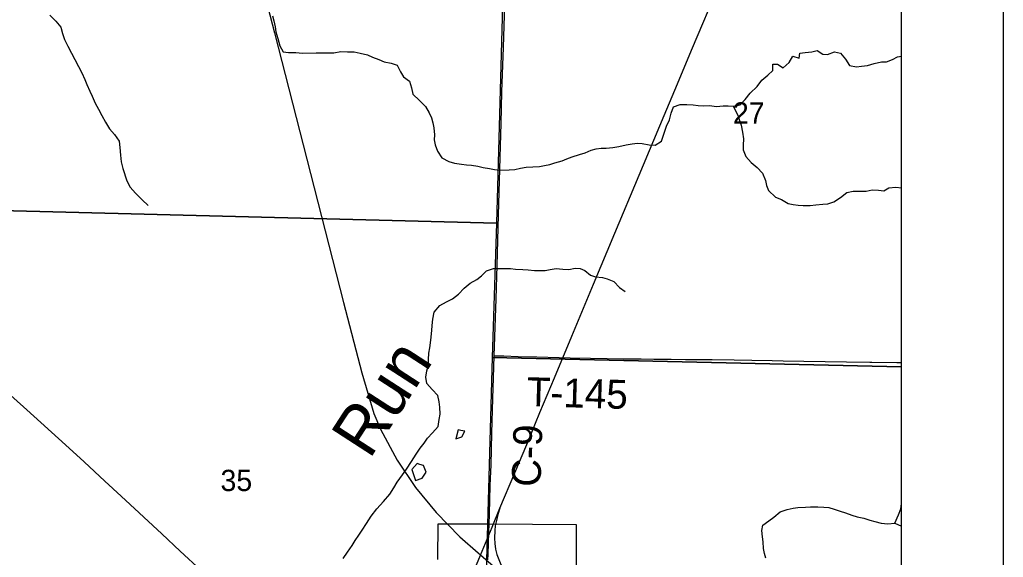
# Model space of a CAD drawing. Extents: x 0 to 34, y 0 to 22.
# Drawn here: x 7.066 to 9, y 15.96 to 17.017 of the extents above; entities that cross this region are included whole.
import ezdxf

# ---------------------------------------------------------------- set-up
doc = ezdxf.new("R2010")
doc.units = 0
for name, color, linetype in [('Default', 7, 'Continuous'), ('GM_X_City_Street', 7, 'Continuous'), ('GM_X_Corporation', 7, 'Continuous'), ('GM_X_County_Road', 7, 'Continuous'), ('GM_X_County_Road_Text', 7, 'Continuous'), ('GM_X_Interchange_Ramps', 7, 'Continuous'), ('GM_X_Major_River', 7, 'Continuous'), ('GM_X_Major_River_Text', 7, 'Continuous'), ('GM_X_Minor_River', 7, 'Continuous'), ('GM_X_Minor_River_Text', 7, 'Continuous'), ('GM_X_Section', 7, 'Continuous'), ('GM_X_Unincorporated_Location', 7, 'Continuous'), ('GM_X_US_Shield', 7, 'Continuous'), ('SH_Cut_Line', 7, 'Continuous'), ('SH_Text', 7, 'Continuous')]:
    doc.layers.add(name, color=color, linetype=linetype)

msp = doc.modelspace()

# ---------------------------------------------------------------- linework, layer by layer
at = {"layer": 'Default'}
msp.add_lwpolyline([(8.8, 14), (8.8, 18.8069)], dxfattribs=at)
for points in [[(8.8, 16.334), (8.8, 17.3506), (8.0236, 17.3548), (8.0033, 16.6164), (7.9948, 16.3527)], [(8.8, 15.3246), (8.8, 16.334), (7.9948, 16.3527), (7.9737, 15.6015), (7.9679, 15.3374)]]:
    msp.add_lwpolyline(points, close=True, dxfattribs=at)
at = {"layer": 'GM_X_City_Street'}
for points in [[(7.9989, 16.356), (8.0025, 16.468), (8.0046, 16.5332), (8.0075, 16.6325), (8.0103, 16.7226), (8.0122, 16.7909), (8.0126, 16.8127), (8.0141, 16.8748), (8.017, 16.9617), (8.021, 17.0901)], [(7.989, 16.0249), (7.9895, 16.0453), (7.9911, 16.1012), (7.9927, 16.1416), (7.9943, 16.2037), (7.9964, 16.2721), (7.9976, 16.3125), (7.9989, 16.356)], [(7.9867, 15.9546), (7.9871, 15.9656), (7.9887, 16.009), (7.989, 16.0249)]]:
    msp.add_lwpolyline(points, dxfattribs=at)
at = {"layer": 'GM_X_Corporation'}
for p, q in [((7.9673, 15.9687), (7.9718, 15.9648)), ((7.9718, 15.9648), (8.0563, 15.8914))]:
    msp.add_line(p, q, dxfattribs=at)
for points in [[(6.5927, 20.8), (6.6173, 20.7022), (6.732, 20.2629), (6.8332, 19.8757), (6.9052, 19.5948), (7.0125, 19.1776), (7.1431, 18.6694), (7.2218, 18.3603), (7.335, 17.9018), (7.5012, 17.2442), (7.5672, 16.9911), (7.6376, 16.714), (7.7025, 16.4605), (7.7388, 16.3223), (7.7626, 16.2427), (7.7756, 16.2117), (7.8081, 16.1506), (7.8441, 16.0969), (7.8846, 16.0477), (7.9314, 15.9998), (7.9673, 15.9687)], [(7.9573, 15.9292), (7.972, 15.9642), (7.995, 16.0193), (8.0101, 16.0566), (8.0396, 16.1259), (8.063, 16.1817), (8.0889, 16.2441), (8.1175, 16.3124), (8.1518, 16.3948), (8.1945, 16.4965), (8.2364, 16.597), (8.2842, 16.7108), (8.3333, 16.828), (8.3542, 16.8783), (8.3889, 16.9613), (8.4405, 17.0841)], [(8.0101, 16.0566), (8.0064, 16.0438), (8.0032, 16.0324), (8.0011, 16.0214), (8, 16.0122), (7.9995, 15.9972), (8, 15.9869), (8.0018, 15.9759), (8.0044, 15.965), (8.008, 15.9554), (8.0122, 15.9455), (8.0171, 15.9362), (8.0217, 15.929), (8.0261, 15.9226), (8.0314, 15.9163), (8.0364, 15.9108), (8.0427, 15.9049), (8.0587, 15.8914), (8.5043, 15.5105), (8.8, 15.2581)]]:
    msp.add_lwpolyline(points, dxfattribs=at)
at = {"layer": 'GM_X_County_Road'}
msp.add_lwpolyline([(7.0027, 16.3195), (7.0291, 16.2956), (7.0799, 16.2498), (7.1558, 16.1809), (7.1925, 16.1473), (7.2336, 16.1094), (7.2657, 16.08), (7.3452, 16.0057), (7.3814, 15.9718), (7.4226, 15.9339), (7.4544, 15.9041), (7.4861, 15.8744), (7.4979, 15.8643), (7.5018, 15.8606), (7.5256, 15.8381), (7.5518, 15.8138)], dxfattribs=at)
at = {"layer": 'GM_X_Interchange_Ramps'}
msp.add_lwpolyline([(7.9989, 16.356), (8.0181, 16.3556), (8.0458, 16.3548), (8.083, 16.3539), (8.1265, 16.3527), (8.1482, 16.3522), (8.1886, 16.3511), (8.2538, 16.3501), (8.2879, 16.3496), (8.3128, 16.3493), (8.3469, 16.349), (8.3748, 16.3488), (8.4276, 16.3483), (8.4711, 16.3478), (8.5053, 16.3475), (8.5456, 16.3469), (8.5673, 16.3463), (8.6077, 16.3455), (8.6915, 16.3442), (8.7375, 16.3436), (8.7412, 16.3436), (8.7909, 16.3428), (8.8, 16.3427)], dxfattribs=at)
at = {"layer": 'GM_X_Major_River'}
for points in [[(7.9332, 16.209), (7.9281, 16.2101), (7.9236, 16.1926)], [(7.9236, 16.1926), (7.9354, 16.1964), (7.9411, 16.2074), (7.9332, 16.209)], [(7.8525, 16.1425), (7.8475, 16.144), (7.8368, 16.1326), (7.8444, 16.111)], [(7.8444, 16.111), (7.857, 16.1151), (7.865, 16.1269), (7.86, 16.1402), (7.8525, 16.1425)]]:
    msp.add_lwpolyline(points, dxfattribs=at)
at = {"layer": 'GM_X_Section'}
for points in [[(7.1254, 17.0258), (7.1372, 17.0137), (7.1467, 17.0019), (7.1502, 16.9894), (7.1544, 16.9777), (7.1609, 16.9644), (7.1681, 16.9512), (7.1742, 16.9387), (7.1815, 16.9247), (7.1884, 16.9122), (7.1941, 16.8993), (7.1979, 16.8891), (7.2037, 16.8762), (7.2086, 16.8664), (7.2147, 16.8524), (7.2209, 16.8406), (7.2277, 16.8285), (7.235, 16.8153), (7.2426, 16.802), (7.2525, 16.7907), (7.2613, 16.7778), (7.2632, 16.7653), (7.264, 16.7505), (7.2652, 16.7372), (7.2691, 16.7243), (7.2767, 16.7001), (7.2832, 16.6876), (7.2935, 16.6759), (7.3068, 16.6626), (7.3186, 16.6513)], [(7.5633, 17.0244), (7.5656, 17.0142), (7.5686, 17.0024), (7.5694, 16.9925), (7.5736, 16.9796), (7.5777, 16.9655), (7.5842, 16.9534), (7.5945, 16.9522), (7.6086, 16.9519), (7.6222, 16.9511), (7.6489, 16.9518), (7.6591, 16.9515), (7.6702, 16.9518), (7.6839, 16.9514), (7.6976, 16.9541), (7.7105, 16.9533), (7.7234, 16.9533), (7.7356, 16.9507), (7.7497, 16.9476), (7.7596, 16.9431), (7.7721, 16.9381), (7.7828, 16.9339), (7.7965, 16.9313), (7.8079, 16.9271), (7.8147, 16.9142), (7.8204, 16.9043), (7.8322, 16.8959), (7.8364, 16.883), (7.839, 16.8701), (7.852, 16.8575), (7.8641, 16.8458), (7.8714, 16.8336), (7.8755, 16.8237), (7.8782, 16.8142), (7.8801, 16.804), (7.8816, 16.7903), (7.8812, 16.7808), (7.8831, 16.7709), (7.8873, 16.7584), (7.8957, 16.7451), (7.9097, 16.7378), (7.9208, 16.7344), (7.9348, 16.7325), (7.9447, 16.7314), (7.9546, 16.7306), (7.9668, 16.7287), (7.9771, 16.726), (7.99, 16.7238), (7.9995, 16.7222), (8.0094, 16.7211), (8.0284, 16.7218), (8.0394, 16.7222), (8.0508, 16.7249), (8.0619, 16.7268), (8.0752, 16.7275), (8.0881, 16.7283), (8.098, 16.7302), (8.1083, 16.7317), (8.1182, 16.7351), (8.1323, 16.7393), (8.1418, 16.7431), (8.152, 16.7469), (8.1669, 16.7514), (8.1779, 16.7552), (8.1897, 16.7602), (8.1992, 16.7628), (8.2095, 16.7643), (8.219, 16.7643), (8.2319, 16.7655), (8.2437, 16.7674), (8.2582, 16.7704)], [(8.2582, 16.7704), (8.2704, 16.7727), (8.2806, 16.7742), (8.2901, 16.7734), (8.3035, 16.7708), (8.3156, 16.77), (8.3278, 16.778), (8.3312, 16.7875), (8.3347, 16.7977), (8.3377, 16.8072), (8.3434, 16.8201), (8.3468, 16.8327), (8.3518, 16.8456), (8.3644, 16.8498), (8.378, 16.8501), (8.3902, 16.8494), (8.3997, 16.8482), (8.4096, 16.8475), (8.4222, 16.8478), (8.4359, 16.8463), (8.4492, 16.8471), (8.4587, 16.8474), (8.469, 16.8467), (8.4827, 16.8493), (8.4925, 16.8596), (8.5024, 16.8725), (8.5158, 16.8854), (8.5249, 16.8976), (8.5371, 16.9078), (8.547, 16.9166), (8.5466, 16.9295), (8.5561, 16.9291), (8.5671, 16.9222), (8.5789, 16.9325), (8.5858, 16.9447), (8.5983, 16.9412), (8.6002, 16.9507), (8.6105, 16.9522), (8.6234, 16.9534), (8.6337, 16.956), (8.6451, 16.9492), (8.6546, 16.9481), (8.668, 16.9534), (8.6801, 16.9507), (8.69, 16.9389), (8.6976, 16.9268), (8.7113, 16.9237), (8.7212, 16.9256), (8.733, 16.9264), (8.7459, 16.9305), (8.7604, 16.934), (8.7703, 16.934), (8.7821, 16.9385), (8.7916, 16.9438), (8.8, 16.945)], [(8.469, 16.8467), (8.4777, 16.8292), (8.4815, 16.8186), (8.4845, 16.8091), (8.4872, 16.7958), (8.4891, 16.7825), (8.4887, 16.7703), (8.4887, 16.7608), (8.4936, 16.7475), (8.5039, 16.7361), (8.5157, 16.7262), (8.5263, 16.7148), (8.5324, 16.7004), (8.5343, 16.6909), (8.5385, 16.681), (8.5522, 16.6677), (8.5636, 16.6631), (8.5769, 16.6555), (8.5868, 16.6532), (8.5967, 16.6521), (8.6062, 16.6513), (8.6199, 16.6517), (8.6313, 16.6528), (8.645, 16.654), (8.6549, 16.6547), (8.6667, 16.6585), (8.6796, 16.6669), (8.6922, 16.6771), (8.7047, 16.6798), (8.7177, 16.6794), (8.7302, 16.6794), (8.7424, 16.6824), (8.7546, 16.6817), (8.7652, 16.6805), (8.7751, 16.6862), (8.7888, 16.6877), (8.8, 16.6859)], [(7.8742, 16.3868), (7.8765, 16.4058), (7.8773, 16.4157), (7.878, 16.4278), (7.8807, 16.4415), (7.8921, 16.4548), (7.9054, 16.462), (7.9168, 16.4677), (7.9286, 16.4768), (7.9397, 16.489), (7.9515, 16.4985), (7.9648, 16.5057), (7.9743, 16.5133), (7.9838, 16.5228), (7.9975, 16.5273), (8.031, 16.5273), (8.0409, 16.5265), (8.0553, 16.5254), (8.0656, 16.525), (8.0781, 16.5239), (8.0991, 16.5239), (8.1093, 16.5254), (8.1208, 16.5277), (8.1337, 16.5265), (8.1455, 16.5254), (8.1584, 16.528), (8.1679, 16.5276), (8.1774, 16.5238), (8.1885, 16.5147), (8.1984, 16.5109), (8.2117, 16.5101), (8.2212, 16.5075), (8.2341, 16.5018), (8.2451, 16.49), (8.2565, 16.4824)], [(7.7017, 15.9571), (7.7108, 15.9697), (7.7196, 15.983), (7.7257, 15.9928), (7.7329, 16.0031), (7.7394, 16.0133), (7.7481, 16.0263), (7.7573, 16.0403), (7.7683, 16.0547), (7.7816, 16.0692), (7.7938, 16.084), (7.8018, 16.0965), (7.8083, 16.1075), (7.8186, 16.1216), (7.8262, 16.133), (7.8364, 16.1478), (7.8452, 16.1622), (7.8536, 16.1744), (7.8612, 16.1839), (7.868, 16.1942), (7.8779, 16.2044), (7.8886, 16.2166), (7.8909, 16.2306), (7.8928, 16.2409), (7.892, 16.2546), (7.8909, 16.2656), (7.8879, 16.2777), (7.8772, 16.2899), (7.8666, 16.3013), (7.8643, 16.3138), (7.8666, 16.3264), (7.87, 16.3382), (7.8696, 16.3484), (7.8704, 16.3613), (7.8723, 16.3716), (7.8742, 16.3868)], [(8.5332, 15.958), (8.5302, 15.9675), (8.5283, 15.977), (8.5276, 15.9899), (8.5264, 15.9998), (8.5249, 16.0127), (8.5272, 16.0229), (8.539, 16.0313), (8.5485, 16.0389), (8.5614, 16.0491), (8.5748, 16.0537), (8.5865, 16.0563), (8.5961, 16.0575), (8.6109, 16.0582), (8.6208, 16.059), (8.6356, 16.059), (8.6474, 16.0586), (8.6569, 16.0578), (8.6676, 16.0544), (8.6794, 16.0502), (8.69, 16.0472), (8.7022, 16.0426), (8.7124, 16.0392), (8.7258, 16.0369), (8.7375, 16.0327), (8.7471, 16.0301), (8.76, 16.027), (8.7729, 16.0255), (8.7866, 16.027), (8.7999, 16.0209), (8.8, 16.0209)], [(8.7866, 16.027), (8.7942, 16.043), (8.7988, 16.0551), (8.7996, 16.0654), (8.8, 16.0663)]]:
    msp.add_lwpolyline(points, dxfattribs=at)
at = {"layer": 'GM_X_Unincorporated_Location'}
for points in [[(7.0045, 17.6571), (8.0227, 17.628), (8.0236, 17.3548), (8.0033, 16.6164), (7.0019, 16.6421)], [(8.0033, 16.6164), (7.9948, 16.3527), (7.9737, 15.6015), (6.9963, 15.6339), (7.0019, 16.6421)]]:
    msp.add_lwpolyline(points, close=True, dxfattribs=at)
at = {"layer": 'GM_X_US_Shield'}
msp.add_lwpolyline([(7.8881, 15.9555), (7.8888, 16.0258), (7.9887, 16.0254), (8.1598, 16.0244), (8.1608, 15.6804)], dxfattribs=at)
at = {"layer": 'SH_Cut_Line'}
msp.add_line((9, 21), (9, 14), dxfattribs=at)
at = {"layer": 'SH_Text'}
msp.add_lwpolyline([(2.9377, 14), (8.8, 14), (8.8, 20.8), (2.9842, 20.8), (2.984, 20.7397), (2.9904, 20.3395), (2.9796, 19.7242), (2.9753, 18.7199), (2.9708, 17.6769), (2.9623, 15.7101), (2.9479, 14.7065)], close=True, dxfattribs=at)

# ---------------------------------------------------------------- texts
at = {"layer": 'GM_X_County_Road_Text'}
msp.add_text('T-145', height=0.05682, rotation=358.3151, dxfattribs=at).set_placement((8.0624, 16.2571))
at = {"layer": 'GM_X_Major_River_Text'}
for s, p in [('27', (8.4683, 16.8124)), ('35', (7.4608, 16.0899))]:
    msp.add_text(s, height=0.04186, rotation=0, dxfattribs=at).set_placement(p)
at = {"layer": 'GM_X_Minor_River'}
msp.add_text('Run', height=0.09471, rotation=57.0832, dxfattribs=at).set_placement((7.7538, 16.1507))
at = {"layer": 'GM_X_Minor_River_Text'}
msp.add_text('C-9', height=0.05682, rotation=88.1416, dxfattribs=at).set_placement((8.0899, 16.0976))

doc.saveas('drawing.dxf')
